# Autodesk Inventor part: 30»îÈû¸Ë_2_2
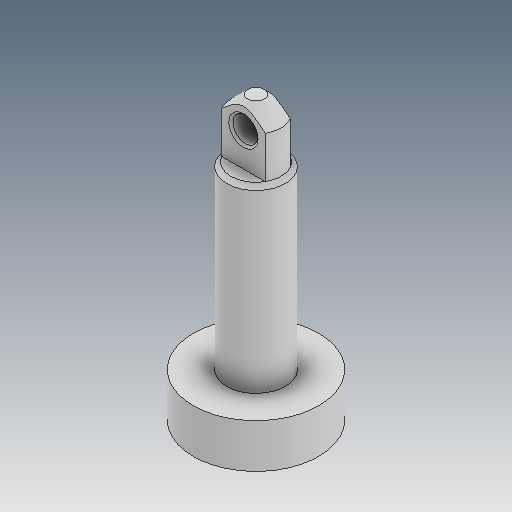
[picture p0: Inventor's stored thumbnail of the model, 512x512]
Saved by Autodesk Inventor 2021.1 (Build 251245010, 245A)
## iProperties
Created: 2019-04
Part Number: 30»îÈû¸Ë_2_2
Material: Ogólny
Document SubType Name: Modeling
Designer: user
Density: 1 g/cm^3
Appearance: Domyślna
Author: user
Revision Number: ÈÎºÎ
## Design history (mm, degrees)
feature "ÊäÈë1"
node "Bryła1"
